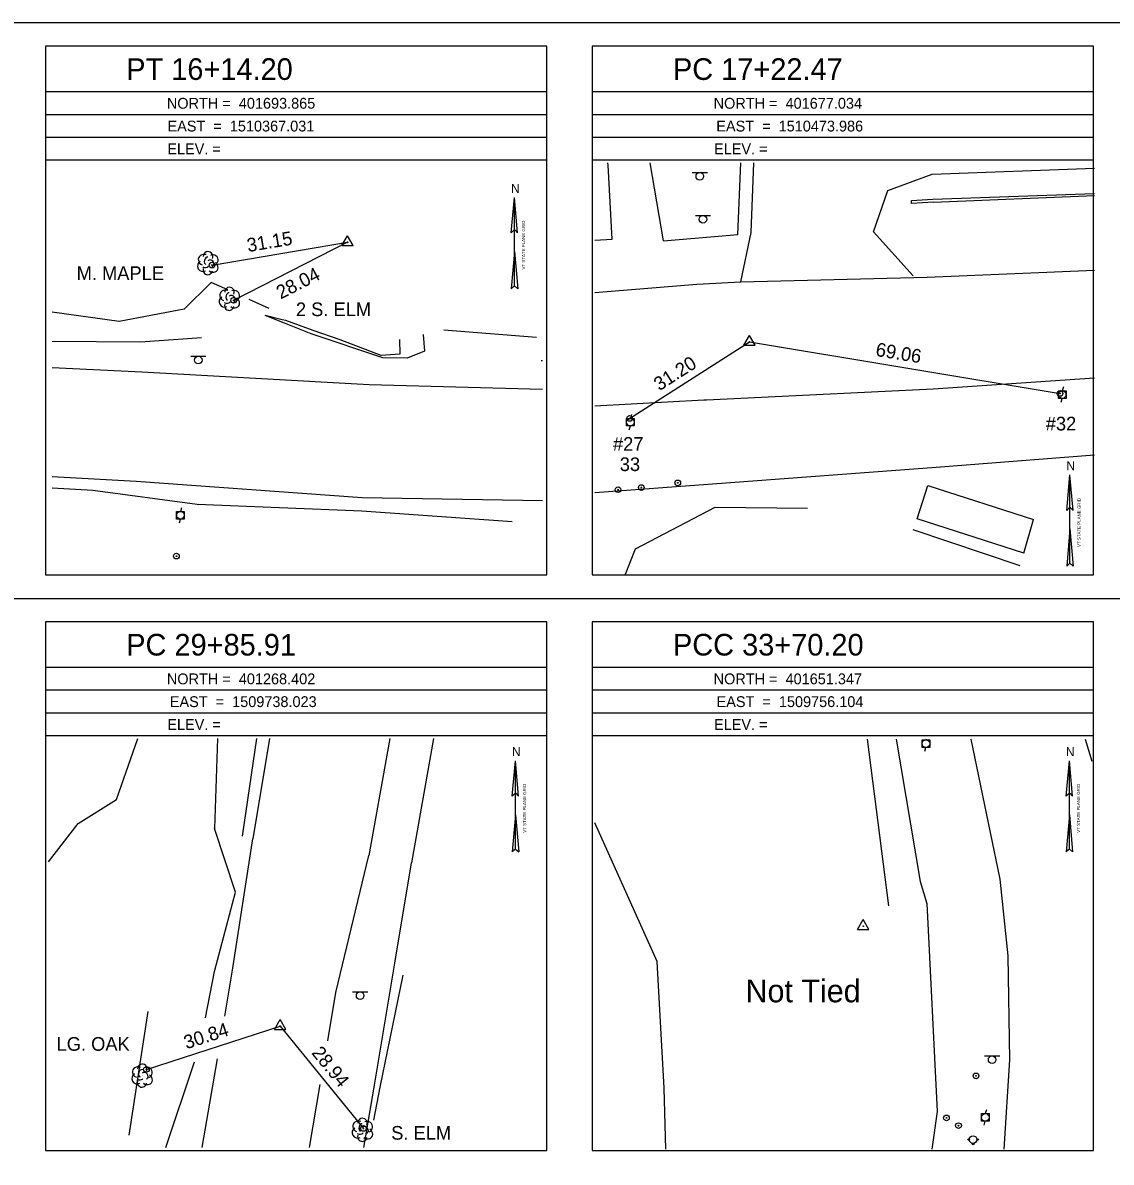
# Model space of a CAD drawing. Extents: x 1508412 to 1509054, y 401108 to 401963.
# Drawn here: x 1508681.9 to 1508920.8, y 401277.6 to 401527.7 of the extents above; entities that cross this region are included whole.
import ezdxf

# ---------------------------------------------------------------- set-up
doc = ezdxf.new("R2010")
doc.units = 0
for name, color, linetype in [('BSUBM', 7, 'Continuous'), ('CBP', 7, 'Continuous'), ('CPH', 7, 'Continuous'), ('DD', 7, 'Continuous'), ('Default', 7, 'Continuous'), ('L_C', 7, 'Continuous'), ('LAPB', 7, 'Continuous'), ('LAWA', 7, 'Continuous'), ('LBC', 7, 'Continuous'), ('LDEFAULT', 7, 'Continuous'), ('Level 5', 7, 'Continuous'), ('LFNC', 7, 'Continuous'), ('LTD', 7, 'Continuous'), ('LW', 7, 'Continuous'), ('LWS', 7, 'Continuous'), ('NBL1', 7, 'Continuous'), ('NBL2', 7, 'Continuous'), ('NNA_P', 7, 'Continuous'), ('PET', 7, 'Continuous'), ('RDG', 7, 'Continuous'), ('RGR', 7, 'Continuous'), ('SSGN', 7, 'Continuous'), ('U_C', 7, 'Continuous'), ('UP', 7, 'Continuous'), ('UPGW', 7, 'Continuous'), ('UWFH', 7, 'Continuous')]:
    doc.layers.add(name, color=color, linetype=linetype)

msp = doc.modelspace()

# ---------------------------------------------------------------- linework, layer by layer
at = {"layer": 'BSUBM'}
for points in [[(1508769.78, 401459.3), (1508770.05, 401455.68), (1508766.27, 401454.11), (1508760.9, 401454.19), (1508745.2, 401459.44), (1508739.37, 401461.78), (1508735.07, 401463.48)], [(1508764.62, 401458.17), (1508764.65, 401454.99), (1508760.57, 401454.7), (1508751.56, 401458.15), (1508745.64, 401460.19), (1508739.64, 401462.34), (1508738.87, 401462.55), (1508735.07, 401463.48)]]:
    msp.add_lwpolyline(points, dxfattribs=at)
at = {"layer": 'CBP'}
for centre, radius in [((1508723.44, 401474.53), 0.625), ((1508723.44, 401474.53), 0.0833), ((1508728.19, 401466.8), 0.625), ((1508728.19, 401466.8), 0.0833), ((1508909.56, 401446.36), 0.625), ((1508909.56, 401446.36), 0.0833), ((1508815.1, 401440.88), 0.625), ((1508815.1, 401440.88), 0.0833), ((1508709.05, 401298.01), 0.625), ((1508709.05, 401298.01), 0.0833), ((1508756.66, 401285.04), 0.625), ((1508756.66, 401285.04), 0.0833)]:
    msp.add_circle(centre, radius, dxfattribs=at)
at = {"layer": 'CPH'}
for p, q in [((1508751.92, 401478.82), (1508753.17, 401480.98)), ((1508751.92, 401478.82), (1508754.42, 401478.82)), ((1508754.42, 401478.82), (1508753.17, 401480.98)), ((1508753.17, 401479.54), (1508753.17, 401479.54)), ((1508840.17, 401456.94), (1508841.42, 401459.1)), ((1508842.67, 401456.94), (1508841.42, 401459.1)), ((1508840.17, 401456.94), (1508842.67, 401456.94)), ((1508841.42, 401457.66), (1508841.42, 401457.66)), ((1508865.13, 401328.71), (1508866.38, 401330.88)), ((1508867.63, 401328.71), (1508866.38, 401330.88)), ((1508866.38, 401329.43), (1508866.38, 401329.43)), ((1508865.13, 401328.71), (1508867.63, 401328.71)), ((1508737.16, 401306.78), (1508738.41, 401308.94)), ((1508739.66, 401306.78), (1508738.41, 401308.94)), ((1508737.16, 401306.78), (1508739.66, 401306.78)), ((1508738.41, 401307.5), (1508738.41, 401307.5))]:
    msp.add_line(p, q, dxfattribs=at)
for centre in [(1508753.17, 401479.54), (1508841.42, 401457.66), (1508866.38, 401329.43), (1508738.41, 401307.5)]:
    msp.add_circle(centre, 0.0833, dxfattribs=at)
at = {"layer": 'DD'}
msp.add_lwpolyline([(1508733.23, 401370.64), (1508730.06, 401349.2)], dxfattribs=at)
at = {"layer": 'Default'}
for p, q in [((1508723.44, 401474.53), (1508753.17, 401479.54)), ((1508753.17, 401479.54), (1508728.19, 401466.8)), ((1508815.1, 401440.88), (1508841.42, 401457.66)), ((1508841.42, 401457.66), (1508909.56, 401446.36)), ((1508709.05, 401298.01), (1508738.41, 401307.5)), ((1508738.41, 401307.5), (1508756.66, 401285.04))]:
    msp.add_line(p, q, dxfattribs=at)
at = {"layer": 'LAPB'}
for points in [[(1508822.51, 401479.85), (1508819.58, 401496.98)], [(1508822.51, 401479.85), (1508838.81, 401481.22), (1508839.47, 401496.98)]]:
    msp.add_lwpolyline(points, dxfattribs=at)
at = {"layer": 'LAWA'}
for points in [[(1508687.53, 401343.55), (1508694.05, 401351.98), (1508702.45, 401357.22), (1508707.15, 401370.64)], [(1508724.63, 401370.64), (1508723.97, 401350.86)], [(1508867.21, 401370.5), (1508871.92, 401333.92)], [(1508823.01, 401280.48), (1508822.65, 401293.87), (1508821.14, 401321.72), (1508807.44, 401352.1)], [(1508728.62, 401336.92), (1508723.97, 401350.86)], [(1508722, 401309.32), (1508723.98, 401319.48), (1508728.62, 401336.92)], [(1508758.97, 401286.87), (1508760.32, 401294.14), (1508765.42, 401318.69)], [(1508713.3, 401280.89), (1508719.62, 401299.63)]]:
    msp.add_lwpolyline(points, dxfattribs=at)
at = {"layer": 'LBC'}
for points in [[(1508878.2, 401418.81), (1508880.58, 401426.15), (1508903.77, 401418.73)], [(1508901.62, 401411.34), (1508878.2, 401418.81)], [(1508901.62, 401411.34), (1508903.77, 401418.73)]]:
    msp.add_lwpolyline(points, dxfattribs=at)
at = {"layer": 'LDEFAULT'}
msp.add_lwpolyline([(1508814.21, 401406.7), (1508816.42, 401412.26), (1508833.86, 401421.43), (1508854.17, 401421.21)], dxfattribs=at)
at = {"layer": 'LFNC'}
for points in [[(1508807.44, 401479.99), (1508811.25, 401480.25), (1508810.36, 401496.5), (1508810.32, 401496.98)], [(1508688.38, 401457.83), (1508707.74, 401457.68), (1508721.15, 401458.61)], [(1508807.44, 401424.65), (1508833.28, 401426.51), (1508882.37, 401430.18), (1508917.1, 401432.87)], [(1508877.27, 401416.49), (1508900.71, 401408.61)], [(1508772.08, 401370.64), (1508767.2, 401343.31)], [(1508763.57, 401321.31), (1508767.2, 401343.31)], [(1508756.74, 401280.89), (1508759.11, 401294.56), (1508763.57, 401321.31)], [(1508705.24, 401283.59), (1508709.46, 401310.68)]]:
    msp.add_lwpolyline(points, dxfattribs=at)
at = {"layer": 'LTD'}
for p, q in [((1508722.51, 401475.01), (1508722.51, 401475.01)), ((1508722.51, 401475.01), (1508722.51, 401475.01)), ((1508727.22, 401467.18), (1508727.22, 401467.18)), ((1508727.22, 401467.18), (1508727.22, 401467.18)), ((1508708.08, 401296.7), (1508708.08, 401296.7)), ((1508708.08, 401296.7), (1508708.08, 401296.7)), ((1508756.43, 401284.8), (1508756.43, 401284.8)), ((1508756.43, 401284.8), (1508756.43, 401284.8))]:
    msp.add_line(p, q, dxfattribs=at)
for centre in [(1508722.56, 401476.44), (1508727.27, 401468.62), (1508708.13, 401298.13), (1508756.47, 401286.23)]:
    msp.add_arc(centre, 1.05, 335.5272, 180.9563, dxfattribs=at)
for centre, major_axis, ratio, start_param, end_param in [((1508721.72, 401475.67), (1.21, -0.51), 0.895232, 1.570796, 4.712389), ((1508722.3, 401475.46), (-0.208, -0.792), 0.645439, 3.141593, 6.283185), ((1508723.55, 401475.59), (-1.14, -0.48), 0.949671, 1.570796, 4.712389), ((1508721.43, 401474.3), (0.58, -1.04), 0.959034, 3.141593, 6.283185), ((1508722.05, 401474.26), (-0.625, -0.083), 0.423636, 0, 3.141593), ((1508723.01, 401474.84), (-0.5, 0.667), 0.989748, 3.141593, 6.283185), ((1508723.51, 401474.17), (-1.09, 0.79), 0.841452, 1.570796, 4.712389), ((1508722.51, 401473.51), (0.26, 1.06), 0.942809, 1.570796, 4.712389), ((1508726.43, 401467.85), (1.21, -0.51), 0.895232, 1.570796, 4.712389), ((1508728.27, 401467.77), (-1.14, -0.48), 0.949671, 1.570796, 4.712389), ((1508726.14, 401466.48), (0.58, -1.04), 0.959034, 3.141593, 6.283185), ((1508726.77, 401466.43), (-0.625, -0.083), 0.423636, 0, 3.141593), ((1508727.02, 401467.64), (-0.208, -0.792), 0.645439, 3.141593, 6.283185), ((1508727.72, 401467.02), (-0.5, 0.667), 0.989748, 3.141593, 6.283185), ((1508728.23, 401466.35), (-1.09, 0.79), 0.841452, 1.570796, 4.712389), ((1508727.23, 401465.68), (0.26, 1.06), 0.942809, 1.570796, 4.712389), ((1508707.29, 401297.37), (1.21, -0.51), 0.895232, 1.570796, 4.712389), ((1508707, 401295.99), (0.58, -1.04), 0.959034, 3.141593, 6.283185), ((1508707.87, 401297.16), (-0.208, -0.792), 0.645439, 3.141593, 6.283185), ((1508708.58, 401296.53), (-0.5, 0.667), 0.989748, 3.141593, 6.283185), ((1508709.08, 401295.87), (-1.09, 0.79), 0.841452, 1.570796, 4.712389), ((1508709.12, 401297.28), (-1.14, -0.48), 0.949671, 1.570796, 4.712389), ((1508708.08, 401295.2), (0.26, 1.06), 0.942809, 1.570796, 4.712389), ((1508707.62, 401295.95), (-0.625, -0.083), 0.423636, 0, 3.141593), ((1508755.64, 401285.46), (1.21, -0.51), 0.895232, 1.570796, 4.712389), ((1508757.47, 401285.38), (-1.14, -0.48), 0.949671, 1.570796, 4.712389), ((1508755.34, 401284.09), (0.58, -1.04), 0.959034, 3.141593, 6.283185), ((1508755.97, 401284.05), (-0.625, -0.083), 0.423636, 0, 3.141593), ((1508756.22, 401285.25), (-0.208, -0.792), 0.645439, 3.141593, 6.283185), ((1508756.93, 401284.63), (-0.5, 0.667), 0.989748, 3.141593, 6.283185), ((1508757.43, 401283.96), (-1.09, 0.79), 0.841452, 1.570796, 4.712389), ((1508756.43, 401283.3), (0.26, 1.06), 0.942809, 1.570796, 4.712389)]:
    msp.add_ellipse(centre, major_axis=major_axis, ratio=ratio, start_param=start_param, end_param=end_param, dxfattribs=at)
at = {"layer": 'LW'}
for points in [[(1508876.94, 401488.68), (1508881.66, 401489.01)], [(1508881.66, 401489.01), (1508917.1, 401490.24)], [(1508881.77, 401488.38), (1508917.1, 401489.84)], [(1508876.99, 401488.09), (1508876.94, 401488.68)], [(1508881.77, 401488.38), (1508876.99, 401488.09)]]:
    msp.add_lwpolyline(points, dxfattribs=at)
at = {"layer": 'LWS'}
for points in [[(1508726.88, 401469.07), (1508723.25, 401470.71), (1508717.34, 401464.86), (1508703.09, 401462.15), (1508688.38, 401464.17)], [(1508735.95, 401464.98), (1508731.57, 401466.96)], [(1508794.68, 401458.66), (1508774.33, 401460.25)], [(1508873.63, 401370.5), (1508878.84, 401339.26), (1508880.32, 401334.42), (1508882.61, 401288.8), (1508881.46, 401280.48)]]:
    msp.add_lwpolyline(points, dxfattribs=at)
at = {"layer": 'NBL1'}
msp.add_lwpolyline([(1508411.91, 401107.72), (1509051.91, 401107.72), (1509051.91, 401527.72), (1508411.91, 401527.72)], close=True, dxfattribs=at)
at = {"layer": 'NBL2'}
for p, q in [((1508796.91, 401512.55), (1508686.91, 401512.55)), ((1508916.91, 401512.55), (1508806.91, 401512.55)), ((1508796.91, 401507.55), (1508686.91, 401507.55)), ((1508916.91, 401507.55), (1508806.91, 401507.55)), ((1508796.91, 401502.55), (1508686.91, 401502.55)), ((1508916.91, 401502.55), (1508806.91, 401502.55)), ((1508796.91, 401497.55), (1508686.91, 401497.55)), ((1508916.91, 401497.55), (1508806.91, 401497.55)), ((1508411.91, 401401.38), (1509051.91, 401401.38)), ((1508796.91, 401386.22), (1508686.91, 401386.22)), ((1508916.91, 401386.22), (1508806.91, 401386.22)), ((1508796.91, 401381.22), (1508686.91, 401381.22)), ((1508916.91, 401381.22), (1508806.91, 401381.22)), ((1508796.91, 401376.22), (1508686.91, 401376.22)), ((1508916.91, 401376.22), (1508806.91, 401376.22)), ((1508796.91, 401371.22), (1508686.91, 401371.22)), ((1508916.91, 401371.22), (1508806.91, 401371.22))]:
    msp.add_line(p, q, dxfattribs=at)
for points in [[(1508686.91, 401406.55), (1508796.91, 401406.55), (1508796.91, 401522.55), (1508686.91, 401522.55)], [(1508806.91, 401406.55), (1508916.91, 401406.55), (1508916.91, 401522.55), (1508806.91, 401522.55)], [(1508686.91, 401280.22), (1508796.91, 401280.22), (1508796.91, 401396.22), (1508686.91, 401396.22)], [(1508806.91, 401280.22), (1508916.91, 401280.22), (1508916.91, 401396.22), (1508806.91, 401396.22)]]:
    msp.add_lwpolyline(points, close=True, dxfattribs=at)
at = {"layer": 'NNA_P'}
for p, q in [((1508789.11, 401481.58), (1508789.81, 401489.37)), ((1508789.81, 401469.99), (1508789.81, 401489.37)), ((1508790.5, 401481.58), (1508789.81, 401489.37)), ((1508789.11, 401481.58), (1508789.81, 401482.34)), ((1508790.5, 401481.58), (1508789.81, 401482.34)), ((1508789.81, 401477.52), (1508789.09, 401469.35)), ((1508789.81, 401477.52), (1508790.53, 401469.35)), ((1508789.81, 401469.99), (1508789.09, 401469.35)), ((1508789.81, 401469.99), (1508790.53, 401469.35)), ((1508911.04, 401420.68), (1508911.73, 401428.47)), ((1508911.74, 401409.09), (1508911.73, 401428.47)), ((1508912.43, 401420.68), (1508911.73, 401428.47)), ((1508911.04, 401420.68), (1508911.73, 401421.44)), ((1508912.43, 401420.68), (1508911.74, 401421.44)), ((1508911.74, 401416.62), (1508911.02, 401408.45)), ((1508911.74, 401416.62), (1508912.46, 401408.45)), ((1508911.74, 401409.09), (1508911.02, 401408.45)), ((1508911.74, 401409.09), (1508912.46, 401408.45)), ((1508789.35, 401357.96), (1508790.04, 401365.75)), ((1508790.04, 401346.37), (1508790.04, 401365.75)), ((1508790.73, 401357.96), (1508790.04, 401365.75)), ((1508910.91, 401357.96), (1508911.61, 401365.75)), ((1508911.61, 401346.37), (1508911.61, 401365.75)), ((1508912.3, 401357.96), (1508911.61, 401365.75)), ((1508789.35, 401357.96), (1508790.04, 401358.72)), ((1508790.74, 401357.96), (1508790.04, 401358.72)), ((1508910.91, 401357.96), (1508911.61, 401358.72)), ((1508912.3, 401357.96), (1508911.61, 401358.72)), ((1508790.05, 401353.9), (1508789.32, 401345.73)), ((1508790.04, 401353.9), (1508790.76, 401345.73)), ((1508911.61, 401353.9), (1508910.89, 401345.73)), ((1508911.61, 401353.9), (1508912.33, 401345.73)), ((1508790.04, 401346.37), (1508789.32, 401345.73)), ((1508790.04, 401346.37), (1508790.76, 401345.73)), ((1508911.61, 401346.37), (1508910.89, 401345.73)), ((1508911.61, 401346.37), (1508912.33, 401345.73))]:
    msp.add_line(p, q, dxfattribs=at)
at = {"layer": 'PET'}
for points in [[(1508807.44, 401468.49), (1508829.87, 401470.36), (1508839.54, 401470.88), (1508880.41, 401471.89), (1508917.1, 401473.39)], [(1508688.38, 401452.03), (1508708.04, 401451.12), (1508757.9, 401448.32), (1508795.98, 401447.29)], [(1508807.44, 401443.61), (1508831.42, 401444.95), (1508831.96, 401444.98), (1508881.7, 401447.4), (1508917.1, 401449.82)], [(1508688.38, 401428.13), (1508706.77, 401427.1), (1508756.38, 401423.55), (1508795.98, 401422.9)], [(1508736.09, 401370.64), (1508732.39, 401348.62)], [(1508762.47, 401370.64), (1508757.87, 401344.95)], [(1508889.99, 401370.5), (1508896.33, 401339.78), (1508898.07, 401322.94), (1508898.44, 401300.08), (1508897.26, 401280.48)], [(1508915.07, 401370.5), (1508916.56, 401365.64)], [(1508727.97, 401319.78), (1508732.39, 401348.62)], [(1508750.65, 401314.9), (1508757.87, 401344.95)], [(1508726.24, 401309.7), (1508727.97, 401319.78)], [(1508748.84, 401304.29), (1508750.65, 401314.9)], [(1508721.28, 401280.89), (1508724.63, 401300.33)], [(1508744.85, 401280.89), (1508747.21, 401294.7)]]:
    msp.add_lwpolyline(points, dxfattribs=at)
at = {"layer": 'RDG'}
for points in [[(1508839.54, 401470.88), (1508841.74, 401481.7), (1508842.35, 401496.98)], [(1508871.79, 401490.94), (1508881.48, 401494.48)], [(1508881.48, 401494.48), (1508917.1, 401495.81)], [(1508877.34, 401472.18), (1508868.64, 401481.83), (1508871.79, 401490.94)]]:
    msp.add_lwpolyline(points, dxfattribs=at)
at = {"layer": 'RGR'}
msp.add_lwpolyline([(1508688.38, 401425.67), (1508697.25, 401425.17), (1508720.19, 401422.1), (1508756.3, 401420.59), (1508789.29, 401418.26)], dxfattribs=at)
at = {"layer": 'SSGN'}
for p, q in [((1508828.85, 401494.86), (1508832.18, 401494.86)), ((1508830.5, 401494.02), (1508830.5, 401494.02)), ((1508829.54, 401485.43), (1508832.87, 401485.43)), ((1508831.19, 401484.6), (1508831.19, 401484.6)), ((1508718.77, 401454.52), (1508722.11, 401454.52)), ((1508720.42, 401453.69), (1508720.42, 401453.69)), ((1508795.67, 401453.63), (1508795.98, 401453.63)), ((1508754.3, 401315.03), (1508757.64, 401315.03)), ((1508755.95, 401314.19), (1508755.95, 401314.19)), ((1508893.01, 401300.97), (1508896.35, 401300.97)), ((1508894.66, 401300.13), (1508894.66, 401300.13))]:
    msp.add_line(p, q, dxfattribs=at)
for centre in [(1508830.5, 401494.02), (1508831.19, 401484.6), (1508720.42, 401453.69), (1508755.95, 401314.19), (1508894.66, 401300.13)]:
    msp.add_circle(centre, 0.833, dxfattribs=at)
at = {"layer": 'UP'}
for p, q in [((1508909.21, 401445.29), (1508909.21, 401446.96)), ((1508909.21, 401446.96), (1508910.88, 401446.96)), ((1508910.29, 401447.79), (1508910.04, 401446.96)), ((1508910.88, 401446.96), (1508910.88, 401445.29)), ((1508910.88, 401445.29), (1508909.21, 401445.29)), ((1508909.79, 401444.46), (1508910.04, 401445.29)), ((1508910.04, 401446.12), (1508910.04, 401446.12)), ((1508815.51, 401441.72), (1508815.26, 401440.89)), ((1508814.42, 401439.22), (1508814.42, 401440.89)), ((1508814.42, 401440.89), (1508816.09, 401440.89)), ((1508816.09, 401439.22), (1508814.42, 401439.22)), ((1508815.01, 401438.39), (1508815.26, 401439.22)), ((1508815.26, 401440.06), (1508815.26, 401440.06)), ((1508816.09, 401440.89), (1508816.09, 401439.22)), ((1508716.77, 401421.29), (1508716.52, 401420.45)), ((1508715.68, 401418.79), (1508715.68, 401420.45)), ((1508715.68, 401420.45), (1508717.35, 401420.45)), ((1508717.35, 401418.79), (1508715.68, 401418.79)), ((1508716.27, 401417.95), (1508716.52, 401418.79)), ((1508716.52, 401419.62), (1508716.52, 401419.62)), ((1508717.35, 401420.45), (1508717.35, 401418.79)), ((1508879.3, 401368.66), (1508879.3, 401370.33)), ((1508879.3, 401370.33), (1508880.97, 401370.33)), ((1508880.18, 401370.5), (1508880.13, 401370.33)), ((1508880.13, 401369.5), (1508880.13, 401369.5)), ((1508880.97, 401370.33), (1508880.97, 401368.66)), ((1508880.97, 401368.66), (1508879.3, 401368.66)), ((1508879.88, 401367.83), (1508880.13, 401368.66)), ((1508893.41, 401289.13), (1508893.16, 401288.3)), ((1508892.33, 401286.63), (1508892.33, 401288.3)), ((1508892.33, 401288.3), (1508893.99, 401288.3)), ((1508893.99, 401286.63), (1508892.33, 401286.63)), ((1508892.91, 401285.8), (1508893.16, 401286.63)), ((1508893.16, 401287.46), (1508893.16, 401287.46)), ((1508893.99, 401288.3), (1508893.99, 401286.63))]:
    msp.add_line(p, q, dxfattribs=at)
for centre in [(1508910.04, 401446.12), (1508815.26, 401440.06), (1508716.52, 401419.62), (1508880.13, 401369.5), (1508893.16, 401287.46)]:
    msp.add_circle(centre, 0.833, dxfattribs=at)
at = {"layer": 'UPGW'}
for centre, radius in [((1508817.66, 401425.71), 0.625), ((1508825.66, 401426.74), 0.625), ((1508825.66, 401426.74), 0.0833), ((1508812.55, 401425.24), 0.625), ((1508812.55, 401425.24), 0.0833), ((1508817.66, 401425.71), 0.0833), ((1508715.63, 401410.67), 0.625), ((1508715.63, 401410.67), 0.0833), ((1508891.12, 401296.58), 0.625), ((1508891.12, 401296.58), 0.0833), ((1508884.64, 401287.35), 0.625), ((1508884.64, 401287.35), 0.0833), ((1508887.28, 401285.66), 0.625), ((1508887.28, 401285.66), 0.0833)]:
    msp.add_circle(centre, radius, dxfattribs=at)
at = {"layer": 'UWFH'}
msp.add_line((1508890.49, 401282.61), (1508890.49, 401282.61), dxfattribs=at)
for centre, radius in [((1508889.49, 401282.61), 0.167), ((1508890.49, 401282.61), 0.833), ((1508890.49, 401281.61), 0.167), ((1508891.49, 401282.61), 0.167)]:
    msp.add_circle(centre, radius, dxfattribs=at)

# ---------------------------------------------------------------- texts
at = {"layer": 'Default'}
for s, rotation, p in [('31.15', 9.573, (1508731.36, 401477.38)), ('28.04', 27.0097, (1508738.51, 401466.98)), ('69.06', 350.5887, (1508868.95, 401454.62)), ('31.20', 32.5167, (1508821.62, 401446.82)), ('30.84', 17.9163, (1508717.81, 401302.41)), ('28.94', 309.0913, (1508745.15, 401301.58))]:
    msp.add_text(s, height=3, rotation=rotation, dxfattribs=at).set_placement(p)
at = {"layer": 'L_C'}
for s, p in [('M. MAPLE', (1508693.73, 401471.26)), ('2 S. ELM', (1508741.85, 401463.33)), ('LG. OAK', (1508689.33, 401302.09)), ('S. ELM', (1508762.77, 401282.58))]:
    msp.add_text(s, height=3, dxfattribs=at).set_placement(p)
at = {"layer": 'Level 5'}
msp.add_text('Not Tied', height=5, dxfattribs=at).set_placement((1508840.53, 401312.73))
at = {"layer": 'NBL2'}
for s, height, p in [('    PT 16+14.20    ', 4.75, (1508697.55, 401515.18)), ('    PC 17+22.47    ', 4.75, (1508817.55, 401515.18)), ('NORTH =  401693.865 ', 2.375, (1508713.53, 401508.86)), ('NORTH =  401677.034 ', 2.375, (1508833.53, 401508.86)), ('EAST  =  1510367.031', 2.375, (1508713.67, 401503.86)), ('EAST  =  1510473.986', 2.375, (1508834.12, 401503.86)), ('ELEV. =             ', 2.375, (1508713.63, 401498.86)), ('ELEV. =             ', 2.375, (1508833.63, 401498.86)), ('    PC 29+85.91    ', 4.75, (1508697.55, 401388.84)), ('    PCC 33+70.20   ', 4.75, (1508817.55, 401388.84)), ('NORTH =  401268.402 ', 2.375, (1508713.53, 401382.53)), ('NORTH =  401651.347 ', 2.375, (1508833.53, 401382.53)), ('EAST  =  1509738.023', 2.375, (1508714.18, 401377.53)), ('EAST  =  1509756.104', 2.375, (1508834.18, 401377.53)), ('ELEV. =             ', 2.375, (1508713.63, 401372.53)), ('ELEV. =             ', 2.375, (1508833.63, 401372.53))]:
    msp.add_text(s, height=height, dxfattribs=at).set_placement(p)
at = {"layer": 'NNA_P'}
for p in [(1508789.05, 401490.38), (1508910.97, 401429.48), (1508789.28, 401366.76), (1508910.85, 401366.76)]:
    msp.add_text('N', height=1.97, dxfattribs=at).set_placement(p)
for p in [(1508792.16, 401473.56), (1508914.09, 401412.66), (1508792.39, 401349.94), (1508913.96, 401349.94)]:
    msp.add_text('VT STATE PLANE GRID', height=0.7, rotation=90.0204, dxfattribs=at).set_placement(p)
at = {"layer": 'U_C'}
for s, p in [('#32', (1508906.43, 401438.24)), ('#27', (1508811.44, 401433.78)), ('33', (1508812.93, 401429.33))]:
    msp.add_text(s, height=3, dxfattribs=at).set_placement(p)

doc.saveas('drawing.dxf')
